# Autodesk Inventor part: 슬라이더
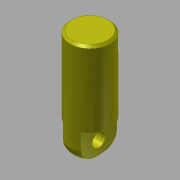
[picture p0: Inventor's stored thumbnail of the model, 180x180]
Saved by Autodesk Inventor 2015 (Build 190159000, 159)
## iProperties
Created: 2016-08
Part Number: 슬라이더
Material: 강철, 탄소
Document SubType Name: Modeling
Designer: mduedu
Density: 7.87 g/cm^3
Appearance: 노란색
Mass: 79.303 g
Surface Area: 30.4538 cm^2
Volume: 10.0766 cm^3
Author: mduedu
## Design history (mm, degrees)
sketch "스케치1"
  geometry: C1 r 9 at (0, 0); 1 further point
  constraints: 1 centre point, 1 coincident
  dimensions: "d0" = 18 diameter of C1
extrude "돌출1" new body sketch "스케치1" distance "d1" = 47; taper "d2" = 0 deg
fillet "모깎기1" dims "d21" = 6
sketch "스케치6"
  geometry: L1 (9, 6)-(9, 47) reference; L2 (-9, 6)-(-9, 47) reference; L3 (9, 47)-(-9, 47) reference; L4 (0, 47)-(0, 0); L5 (9, 13)-(4, 13); L6 (4, 13)-(4, 0); L7 (4, 0)-(9, 0); L8 (9, 0)-(9, 13); L9 (-9, 13)-(-4, 13); L10 (-4, 13)-(-4, 0); L11 (-4, 0)-(-9, 0); L12 (-9, 0)-(-9, 13)
  constraints: 18 end point, 4 symmetric about line, 2 parallel, 2 perpendicular, 1 horizontal, 1 horizontal alignment, 1 midpoint, 1 point on line
  dimensions: "d22" = 13 distance of L7.end L5.start; "d24" = 4 distance between parallel lines of L6 L4
extrude "돌출5" cut sketch "스케치6" stored distance "d25" = 8; taper "d26" = 0 deg
sketch "스케치8"
  geometry: C1 r 3 at (6, 0); 1 further point
  constraints: 1 centre point, 1 horizontal alignment
  dimensions: "d27" = 6 diameter of C1; "d28" = 6 distance of point (0, 0) C1.centre
extrude "돌출6" cut sketch "스케치8" stored distance "d29" = 8; taper "d30" = 0 deg
chamfer "모따기2" distance "d43" = 1; stored, may be unused: second distance "d44" = 2, angle "d45" = 30 deg
node "솔리드1"
